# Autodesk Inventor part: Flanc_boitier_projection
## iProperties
Created: 2011-01
Part Number: Flanc_boitier_projection
Document SubType Name: Modeling
Designer: eric
Density: 1 g/cm^3
Mass: 26.857 g
Surface Area: 377.116 cm^2
Volume: 26.857 cm^3
Author: eric
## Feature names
1. Base1
